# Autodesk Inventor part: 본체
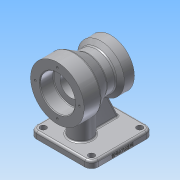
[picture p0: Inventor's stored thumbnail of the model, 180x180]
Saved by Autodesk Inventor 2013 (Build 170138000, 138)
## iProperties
Created: 2019-01
Part Number: 본체
Material: 알루미늄 6061
Document SubType Name: Modeling
Designer: Administrator
Density: 2.71 g/cm^3
Mass: 903.951 g
Surface Area: 601.923 cm^2
Volume: 333.561 cm^3
Author: Administrator
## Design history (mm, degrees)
sketch "스케치1"
  geometry: L1 (-40, 0)-(-40, 40); L2 (-40, 40)-(-15, 40); L3 (-15, 40)-(5.785, 28); L4 (5.785, 28)-(19.126, 28); L5 (19.126, 28)-(25, 35); L6 (25, 35)-(40, 35); L7 (40, 35)-(40, 0); L8 (40, 0)-(-40, 0); 2 further points
  constraints: 16 end point, 3 parallel, 2 perpendicular, 1 coincident, 1 midpoint, 1 vertical
  dimensions: "d0" = 80 diameter of L2 L8; "d2" = 56 diameter of L4 L8; "d3" = 70 diameter of L6 L8; "d4" = 25 distance of L1.end L2.end; "d5" = 15 distance of L5.end L6.end; "d6" = 80 distance of L7.end L1.start; "d8" = 130 deg angle of L4 L5; "d9" = 150 deg angle of L3 L4
revolve "회전1" sketch "스케치1" stored, may be unused: angle "d10" = 90 deg
node "작업 평면1"
sketch "스케치2"
  geometry: L1 (35, 46)-(-57, 46); L2 (-57, 46)-(-57, -46); L3 (-57, -46)-(35, -46); L4 (35, -46)-(35, 46); L5 (35, 46)-(-57, -46); L6 (-57, 46)-(35, -46); L7 (40, 40)-(40, -40) reference; 2 further points
  constraints: 12 end point, 2 parallel, 1 horizontal, 1 horizontal alignment, 1 midpoint, 1 perpendicular
  dimensions: "d12" = 92 distance of L2.end L3.end; "d14" = 92 distance of L1.end L2.end; "d80" = 5 distance between parallel lines of L4 L7
extrude "돌출1" join sketch "스케치2" distance "d15" = 10; taper "d16" = 0 deg
sketch "스케치3"
  geometry: L1 (57, 46)-(-35, 46) reference; L2 (-35, 46)-(-35, -46) reference; C1 r 16 at (-5, 0); 1 further point
  constraints: 1 centre point
  dimensions: "d17" = 32 diameter of C1; "d18" = 30 distance from line of L2 C1.centre; "d19" = 46 distance from line of C1.centre L1
extrude "돌출2" join sketch "스케치3" stored distance "d20" = 10; taper "d21" = 0 deg
sketch "스케치4"
  geometry: L1 (-40, 40)-(-15, 40) reference; L2 (-15, 40)-(5.785, 28) reference; L3 (5.785, 28)-(19.126, 28) reference; L4 (19.126, 28)-(25, 35) reference; L5 (25, 35)-(40, 35) reference; L6 (40, 35)-(40, -35) reference; L7 (40, -35)-(25, -35) reference; L8 (25, -35)-(19.126, -28) reference; L9 (19.126, -28)-(11, -28) reference; L10 (11, -28)-(11, -70) reference; L11 (11, -70)-(57, -70) reference; L12 (57, -70)-(57, -80) reference; L13 (57, -80)-(-35, -80) reference; L14 (-35, -80)-(-35, -70) reference; L15 (-35, -70)-(-21, -70) reference; L16 (-21, -70)-(-21, -40) reference; L17 (-21, -40)-(-40, -40) reference; L18 (-40, -40)-(-40, 40) reference; L19 (47, -70)-(18.199, -8.236); 1 further point
  constraints: 2 end point, 1 point on line
  dimensions: "d24" = 10 distance of L11.end L19.start; "d25" = 25 deg angle of L12 L19
feature "리브1" sketch "스케치4" dims "d26" = 1, "d27" = 10, "d28" = 0, "d29" = 0, "d30" = 1, "d31" = 1
sketch "스케치5"
  geometry: L1 (-21, -40)-(-40, -40) reference; L2 (-40, -40)-(-40, 40) reference; L3 (-40, 40)-(-15, 40) reference; L4 (-15, 40)-(5.785, 28) reference; L5 (5.785, 28)-(19.126, 28) reference; L6 (25, 35)-(40, 35) reference; L7 (40, 35)-(40, -35) reference; L8 (40, -35)-(30.679, -35) reference; L9 (19.126, 28)-(25, 35) reference; L10 (30.679, -35)-(47, -70) reference; L11 (47, -70)-(57, -70) reference; L12 (57, -70)-(57, -80) reference; L13 (57, -80)-(-35, -80) reference; L14 (-35, -80)-(-35, -70) reference; L15 (-35, -70)-(-21, -70) reference; L16 (-21, -70)-(-21, -40) reference; L17 (-40, 26)-(-20, 26); L18 (-20, 26)-(-20, 16); L19 (-20, 16)-(23, 16); L20 (23, 16)-(23, 20); L21 (23, 20)-(40, 20); L22 (40, 20)-(40, 0); L23 (40, 0)-(-40, 0); L24 (-40, 0)-(-40, 26); 1 further point
  constraints: 16 end point, 3 perpendicular, 2 midpoint, 2 parallel, 2 point on line, 1 collinear
  dimensions: "d32" = 52 diameter of L17 L23; "d34" = 32 diameter of L19 L23; "d35" = 40 diameter of L21 L23; "d36" = 20 distance of L17.start L17.end; "d37" = 17 distance of L20.end L21.end
revolve "회전2" sketch "스케치5" stored, may be unused: angle "d38" = 90 deg
sketch "스케치6" dims "d39" = 66
  geometry: C1 r 26 at (0, 0) reference; C2 r 40 at (0, 0) reference; 2 further points
  constraints: 2 vertical alignment, 1 coincident, 2 other
hole "구멍1" sketch "스케치6" at (0, 33) diameter "d40" = 3.242; stored, may be unused: countersink angle "d44" = 90 deg, drill point angle "d46" = 118 deg; dims "d41" = 9, "d42" = 4, "d43" = 2, "d45" = 11
sketch "스케치7" dims "d50" = 55
  geometry: C1 r 20 at (0, 0) reference; C2 r 35 at (0, 0) reference; 2 further points
  constraints: 2 vertical alignment, 1 coincident, 2 other
hole "구멍2" sketch "스케치7" at (0, 27.5) diameter "d51" = 3.242; stored, may be unused: countersink angle "d55" = 90 deg, drill point angle "d57" = 118 deg; dims "d52" = 9, "d53" = 4, "d54" = 2, "d56" = 11
fillet "모깎기1" dims "d61" = 10
sketch "스케치8"
  geometry: C1 r 4.5 at (-25, 36); A1 r 10 centre (-25, 36) between (-25, 46) and (-35, 36) reference; 1 further point
  constraints: 1 centre point, 1 coincident
  dimensions: "d62" = 9 diameter of C1
extrude "돌출3" cut sketch "스케치8" stored distance "d63" = 10; taper "d64" = 0 deg
sketch "스케치9"
  geometry: C1 r 4.5 at (47, 36); A1 r 10 centre (47, 36) between (57, 36) and (47, 46) reference; 1 further point
  constraints: 1 centre point, 1 coincident
  dimensions: "d65" = 9 diameter of C1
extrude "돌출4" cut sketch "스케치9" distance "d66" = 10; taper "d67" = 0 deg
sketch "스케치10"
  geometry: C1 r 4.5 at (-25, -36); A1 r 10 centre (-25, -36) between (-35, -36) and (-25, -46) reference; 1 further point
  constraints: 1 centre point, 1 coincident
  dimensions: "d68" = 9 diameter of C1
extrude "돌출5" cut sketch "스케치10" distance "d69" = 10; taper "d70" = 0 deg
sketch "스케치11"
  geometry: C1 r 4.5 at (47, -36); A1 r 10 centre (47, -36) between (47, -46) and (57, -36) reference; 1 further point
  constraints: 1 centre point, 1 coincident
  dimensions: "d71" = 9 diameter of C1
extrude "돌출6" cut sketch "스케치11" distance "d72" = 10; taper "d73" = 0 deg
fillet "모깎기2" dims "d74" = 1
fillet "모깎기3" dims "d75" = 0.6
fillet "모깎기4" dims "d76" = 3
fillet "모깎기5" dims "d77" = 3
fillet "모깎기7" dims "d79" = 3
fillet "모깎기8" dims "d81" = 2
fillet "모깎기9" dims "d82" = 2
chamfer "모따기1" distance "d83" = 1; stored, may be unused: second distance "d84" = 2, angle "d85" = 45 deg
node "작업 평면2"
sketch "스케치12"
  geometry: L1 (-10, 7)-(-10, 0) reference; L2 (82, 0)-(72, 0) reference; 2 further points
  constraints: 1 other
  dimensions: "d87" = 46 distance from line of point (36, 4) L1; "d88" = 4 distance from line of L2 point (36, 4)
feature "엠보싱1" sketch "스케치12" dims "d89" = 0.5, "d90" = 0
node "솔리드1"
pattern_circular "원형 패턴1" dims angle "d48" = 360 deg
pattern_circular "원형 패턴2" dims angle "d59" = 360 deg
node "절단 모서리 투영1"
node "절단 모서리 투영2"
other parameters: "d86" = 92
